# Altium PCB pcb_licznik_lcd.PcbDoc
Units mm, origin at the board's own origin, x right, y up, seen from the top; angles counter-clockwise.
Board outline 68.45 x 37.59 mm, 2 copper layers (Top Layer, Bottom Layer); 23 components, 34 nets, 133 pads, 10 vias.
Unrouted connection lines stored in the file: 5.
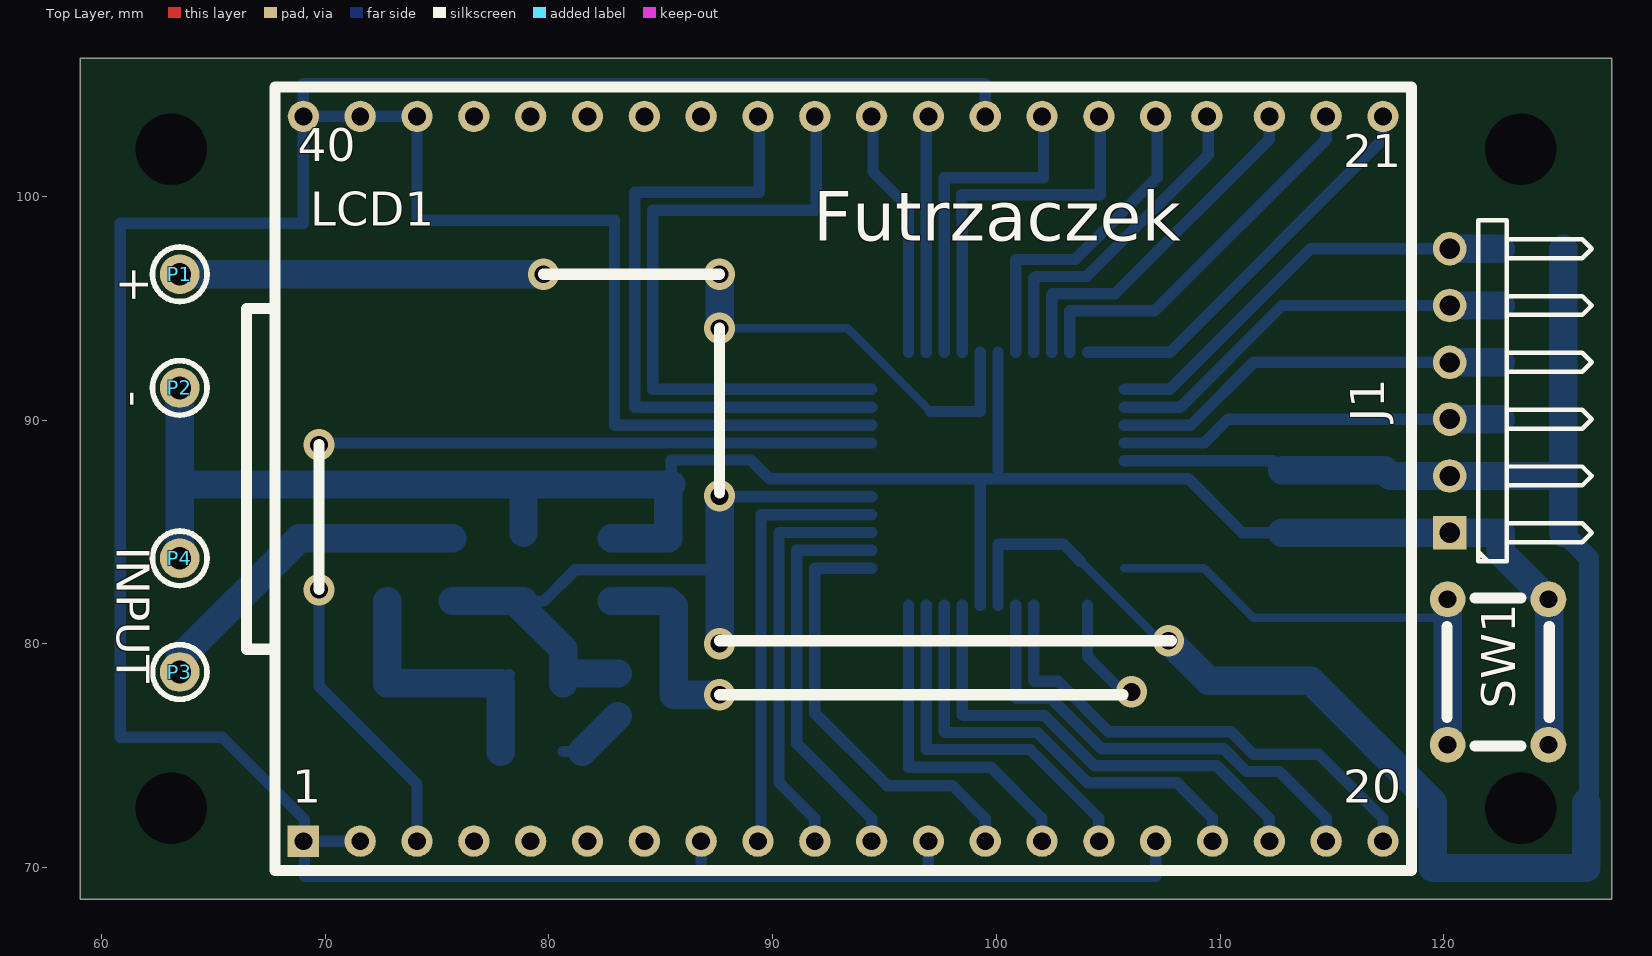
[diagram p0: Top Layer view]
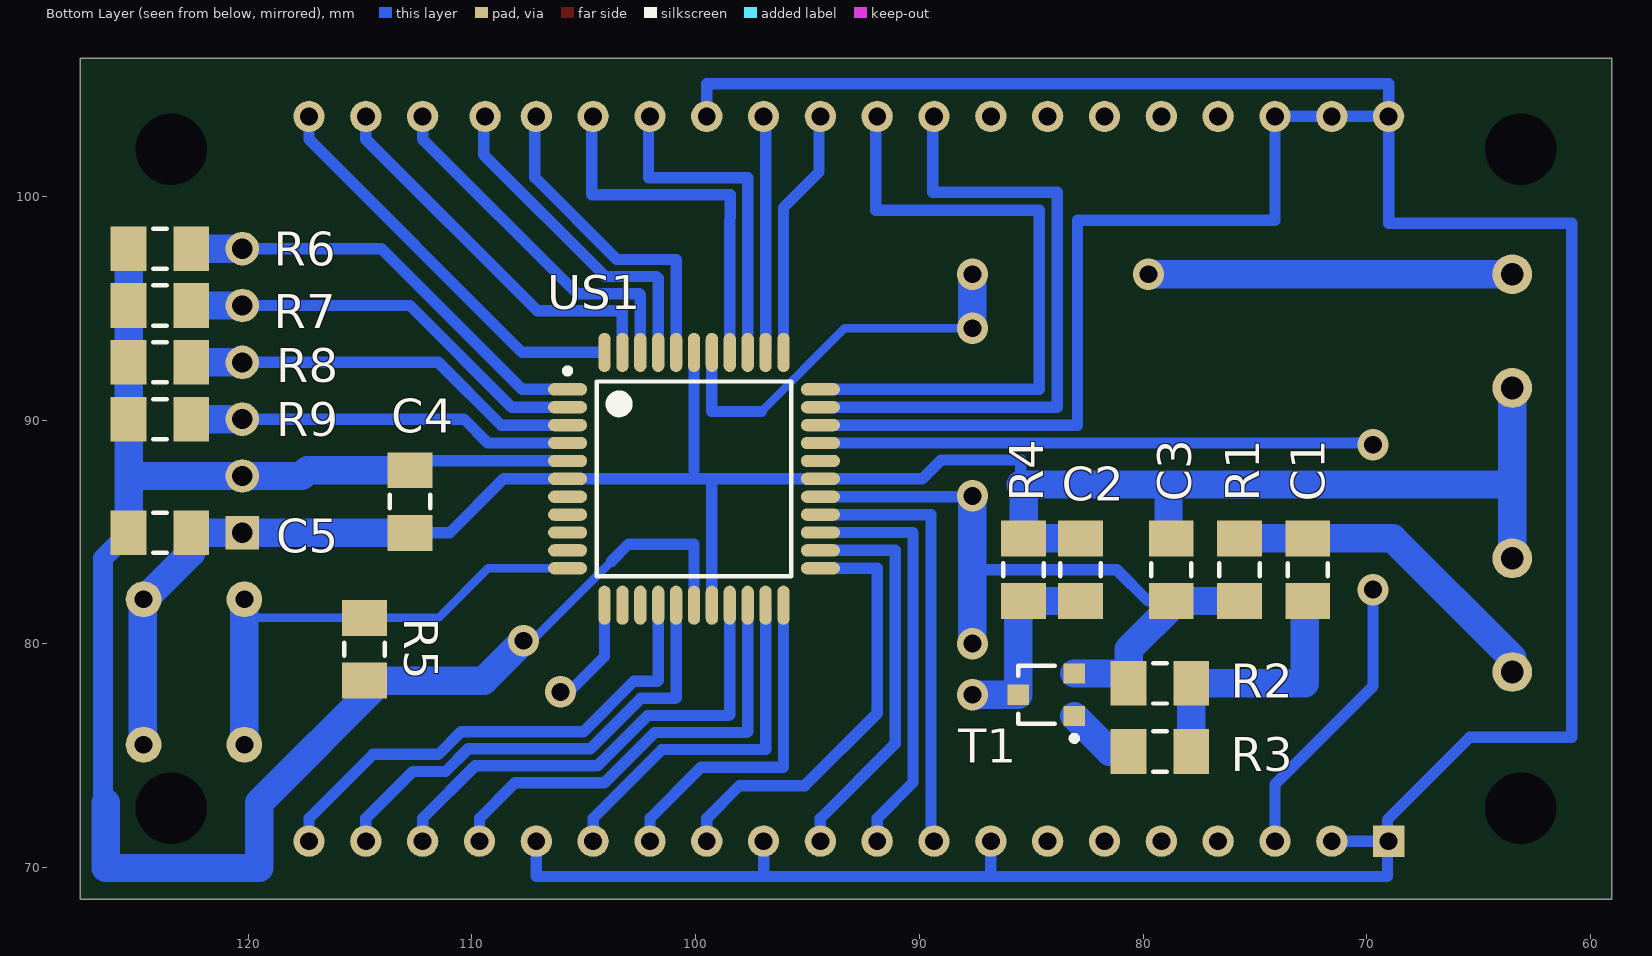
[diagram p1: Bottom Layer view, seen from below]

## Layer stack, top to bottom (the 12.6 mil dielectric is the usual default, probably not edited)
Top Layer: signal copper 0.0356
Dielectric: dielectric 0.32, FR-4, Dk 4.8
Bottom Layer: signal copper 0.0356

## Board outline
59.055,69.977 59.055,106.172 127.508,106.172 127.508,68.58 59.055,68.58

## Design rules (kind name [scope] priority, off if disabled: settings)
Clearance [All] p1: gap=0.254
PolygonConnect [All] p1: connectstyle=Relief reliefconductorwidth=0.254 reliefentries=4 polygonreliefangle="90 Angle"
RoutingVias [All] p1: holewidth=0.711 width=1.27 viastyle="Through Hole" minholewidth=0.711 minwidth=1.27 maxholewidth=0.711 maxwidth=1.27
SilkscreenOverComponentPads [All] p1: minsilkscreentomaskgap=0.254
SolderMaskExpansion [All] p1: expansion=0.102
Width [All] p1: maxlimit=1.27 minlimit=0.381 preferedwidth=0.508
27 further rules are at their usual default settings.

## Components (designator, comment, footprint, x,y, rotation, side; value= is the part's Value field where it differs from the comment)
C1 "100n" MELF-1206 72.644,83.312 r270 bottom
C2 "1u" MELF-1206 82.804,83.312 r270 bottom
C3 "1u" MELF-1206 78.74,83.312 r270 bottom
C4 "100n" MELF-1206 112.776,86.36 r90 bottom
C5 "100n" MELF-1206 123.952,84.963 r0 bottom
J1 "" HDR1X6H 120.269,84.963 r90 top
LCD1 "JH17" "LCD JH17" 94.426,87.376 r0 top
P1 "WE" "pad fi 1mm" 63.5,96.52 r0 top
P2 "WE" "pad fi 1mm" 63.5,91.44 r0 top
P3 "WE" "pad fi 1mm" 63.5,78.74 r0 top
P4 "WE" "pad fi 1mm" 63.5,83.82 r0 top
R1 "100k" MELF-1206 75.692,83.312 r90 bottom
R2 "10k" MELF-1206 79.248,78.232 r180 bottom
R3 "10k" MELF-1206 79.248,75.184 r0 bottom
R4 "10k" MELF-1206 85.344,83.312 r270 bottom
R5 "10k" MELF-1206 114.808,79.756 r270 bottom
R6 "10k" MELF-1206 123.952,97.663 r180 bottom
R7 "10k" MELF-1206 123.952,95.123 r180 bottom
R8 "10k" MELF-1206 123.952,92.583 r180 bottom
R9 "10k" MELF-1206 123.952,90.043 r180 bottom
SW1 "switch 6x6" "tact switch 6x6" 122.428,78.74 r270 top
T1 "BC856" 318-08 84.328,77.724 r90 bottom
US1 "ATmega32L" 44A_N 100.076,87.376 r180 bottom

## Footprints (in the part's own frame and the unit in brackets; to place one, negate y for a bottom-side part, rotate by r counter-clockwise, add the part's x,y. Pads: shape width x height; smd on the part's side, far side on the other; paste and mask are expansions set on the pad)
44A_N [mm] "Thin QFP, 44-Leads, Body 10x10mm, Pitch 0.8mm, IPC Medium Density"
  oval 1.75x0.55 smd: 1(-5.65,4) 2(-5.65,3.2) 3(-5.65,2.4) 4(-5.65,1.6) 5(-5.65,0.8) 6(-5.65,0) 7(-5.65,-0.8) 8(-5.65,-1.6) 9(-5.65,-2.4) 10(-5.65,-3.2) 11(-5.65,-4) 23(5.65,-4) 24(5.65,-3.2) 25(5.65,-2.4) 26(5.65,-1.6) 27(5.65,-0.8) 28(5.65,0) 29(5.65,0.8) 30(5.65,1.6) 31(5.65,2.4) 32(5.65,3.2) 33(5.65,4)
  oval 0.55x1.75 smd: 12(-4,-5.65) 13(-3.2,-5.65) 14(-2.4,-5.65) 15(-1.6,-5.65) 16(-0.8,-5.65) 17(0,-5.65) 18(0.8,-5.65) 19(1.6,-5.65) 20(2.4,-5.65) 21(3.2,-5.65) 22(4,-5.65) 34(4,5.65) 35(3.2,5.65) 36(2.4,5.65) 37(1.6,5.65) 38(0.8,5.65) 39(0,5.65) 40(-0.8,5.65) 41(-1.6,5.65) 42(-2.4,5.65) 43(-3.2,5.65) 44(-4,5.65)
  silkscreen extent -5.77,-4.35 4.35,4.95, body extent -5,-5 5,5, height 1.2
318-08 [mm] "SOT-23; 3 Leads; Body 3.0 x 2.6 mm, inc. leads (LxW max)"
  rect 0.9x0.95 smd: 1(-0.95,-1.25) 2(0.95,-1.25) 3(0,1.25)
  silkscreen extent -2.07,-1.37 1.3,1.25
HDR1X6H [mm] "Connector; Header; 6 Position; Right Angle"
  rect 1.5x1.5 hole 0.9: 1(0,0)
  round 1.5 hole 0.9: 2(2.54,0) 3(5.08,0) 4(7.62,0) 5(10.16,0) 6(12.7,0)
  silkscreen extent -1.27,-6.35 13.97,-1.27
"LCD JH17" [mm]
  rect 1.4x1.4 hole 0.8: 1(-25.4,-16.2)
  round 1.4 hole 0.8: 2(-22.86,-16.2) 3(-20.32,-16.2) 4(-17.78,-16.2) 5(-15.24,-16.2) 6(-12.7,-16.2) 7(-10.16,-16.2) 8(-7.62,-16.2) 9(-5.08,-16.2) 10(-2.54,-16.2) 11(0,-16.2) 12(2.54,-16.2) 13(5.08,-16.2) 14(7.62,-16.2) 15(10.16,-16.2) 16(12.7,-16.2) 17(15.24,-16.2) 18(17.78,-16.2) 19(20.32,-16.2) 20(22.86,-16.2) 21(22.86,16.2) 22(20.32,16.2) 23(17.78,16.2) 24(14.986,16.2) 25(12.7,16.2) 26(10.16,16.2) 27(7.62,16.2) 28(5.08,16.2) 29(2.54,16.2) 30(0,16.2) 31(-2.54,16.2) 32(-5.08,16.2) 33(-7.62,16.2) 34(-10.16,16.2) 35(-12.7,16.2) 36(-15.24,16.2) 37(-17.78,16.2) 38(-20.32,16.2) 39(-22.86,16.2) 40(-25.4,16.2)
  silkscreen extent -27.94,-17.51 24.13,17.51
MELF-1206 [mm] "Metal Electrode Face (MELF) Resistor; Body 3.2 x 1.8 mm (LxDia)"
  rect 1.6x2 smd: 1(-1.4,0) 2(1.4,0)
  silkscreen extent -0.3,-0.9 0.3,0.9, body extent -2.3,-1.1 2.3,1.1, height 1.85
"pad fi 1mm" [mil]
  round 70 hole 40: 1(0,0)
  silkscreen extent -48,-48 48,48
"tact switch 6x6" [mm]
  round 1.6 hole 0.8: 1(3.25,2.25) 2(3.25,-2.25) 3(-3.25,2.25) 4(-3.25,-2.25)
  silkscreen extent -3.3,-2.29 3.3,2.29

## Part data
C1 C2 C3 C4 C5: library part kondensator
J1: library part "Header 6H", "Header, 6-Pin, Right Angle"
LCD1: library part "LCD JH17"
P1 P2 P3 P4: library part Pad, "Pad"
R1 R2 R3 R4 R5 R6 R7 R8 R9: library part rezystor
SW1: library part switch
T1: library part BC856ALT1, "General Purpose Transistor PNP Silicon"
US1: library part ATmega32-16AC, "8-Bit AVR Microcontroller with 32K Bytes of In-System Programmable Flash Memory"

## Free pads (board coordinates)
  round 0 hole 3.2: 0(63.119,72.644) 1(63.119,102.108) 2(123.444,72.644) 3(123.444,102.108)

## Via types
v1: diameter 1.4, hole 0.8, Top Layer to Bottom Layer, 10 vias

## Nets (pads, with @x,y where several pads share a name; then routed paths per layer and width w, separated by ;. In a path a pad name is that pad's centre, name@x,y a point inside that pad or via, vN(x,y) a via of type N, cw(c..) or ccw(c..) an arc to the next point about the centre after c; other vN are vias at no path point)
GND: C2.1 C3.1 C4.1 C5.1 J1.1 P2.1 P4.1 R4.1 SW1.1 SW1.3 US1.6 US1.18 US1.28 US1.39 | length 101.6
  Bottom Layer w0.508: 85.471,87.122 85.471,88.214 89.027,88.214 89.865,87.376 US1.28 US1.6 108.585,87.376 111.001,84.96 C4.1 ; US1.18 99.276,87.287 ; 100.076,87.757 US1.39
  Bottom Layer w1.27: P4.1 63.5,87.376 ; P2.1 63.5,87.376 ; C3.1@78.867,84.966 78.867,87.122 ; 81.534,87.122 78.867,87.122 ; C2.1 R4.1 85.344,86.995 ; 85.471,87.122 78.867,87.122 ; C4.1@112.779,84.963 J1.1 ; C5.1@121.793,84.963 J1.1 ; SW1.1@124.714,75.49 124.714,81.915 122.552,84.077 C5.1 J1.1 ; 63.5,87.376 63.754,87.122 78.867,87.122
NetC1_1: C1.1 P3.1 R1.2 | length 15
  Bottom Layer w1.27: P3.1 63.5,79.375 68.837,84.712 74.676,84.712 R1.2
NetC1_2: C1.2 R2.2 R3.1 | length 12.3
  Bottom Layer w0.508: R2.2 R2.2@78.232,78.616
  Bottom Layer w1.27: C1.2@72.771,81.912 72.771,78.232 R2.2 R3.1
NetC2_2: C2.2 R4.2 T1.3 US1.12 | length 13.4
  Bottom Layer w0.508: US1.12 104.076,79.439 v1@105.664,77.851
  Bottom Layer w1.27: C2.2 R4.2 85.578,81.678 T1.3 v1(87.63,77.724)
  other v1: 106.045,77.851
NetJ1_3: J1.3 R9.2 US1.4 | length 18.8
  Bottom Layer w0.508: US1.4 109.296,88.976 110.363,90.043 R9.2@121.793,90.043
  Bottom Layer w1.27: J1.3 R9.2
NetJ1_4: J1.4 R8.2 US1.3 | length 19.5
  Bottom Layer w0.508: US1.3 108.699,89.776 111.506,92.583 R8.2@121.793,92.583
  Bottom Layer w1.27: J1.4 R8.2
NetJ1_5: J1.5 R7.2 US1.2 | length 20.2
  Bottom Layer w0.508: US1.2 108.229,90.576 112.776,95.123 R7.2@121.793,95.123
  Bottom Layer w1.27: J1.5 R7.2
NetJ1_6: J1.6 R6.2 US1.1 | length 21
  Bottom Layer w0.508: US1.1 107.759,91.376 114.046,97.663 R6.2@121.793,97.663
  Bottom Layer w1.27: J1.6 R6.2
NetLCD1_1: LCD1.1 LCD1.2 LCD1.8 LCD1.12 LCD1.16 LCD1.28 LCD1.38 LCD1.39 LCD1.40 US1.31 | length 166.1
  Bottom Layer w0.508: LCD1.1 LCD1.1@69.075,71.176 ; LCD1.2 LCD1.1@69.075,71.176 ; 86.806,69.658 LCD1.8 ; US1.31 82.931,89.776 82.931,98.933 74.106,98.933 LCD1.38 LCD1.39 LCD1.40 ; 96.966,69.658 LCD1.12 ; LCD1.28@99.501,103.572 99.501,105.029 69.026,105.029 LCD1.40 ; LCD1.16 107.126,69.596 69.075,69.596 LCD1.1@69.075,71.176 ; LCD1.40 69.026,98.806 60.833,98.806 60.833,75.819 65.405,75.819 69.075,72.149 LCD1.1@69.075,71.176
NetLCD1_3: LCD1.3 US1.30 | length 37.8
  Bottom Layer w0.508: v1(69.723,82.423) 69.723,78.105 74.106,73.722 LCD1.3 ; v1(69.723,88.9) 69.799,88.976 US1.30
NetLCD1_9: LCD1.9 US1.26 | length 19.5
  Bottom Layer w0.508: LCD1.9@89.484,71.176 89.484,85.776 US1.26
NetLCD1_10: LCD1.10 US1.25 | length 18.6
  Bottom Layer w0.508: LCD1.10 91.886,72.198 90.284,73.8 90.284,84.976 US1.25
NetLCD1_11: LCD1.11 US1.24 | length 17.7
  Bottom Layer w0.508: LCD1.11 94.426,72.198 91.084,75.54 91.084,84.176 US1.24
NetLCD1_13: LCD1.13 US1.23 | length 19.6
  Bottom Layer w0.508: US1.23 91.884,83.376 91.884,76.899 95.123,73.66 98.044,73.66 99.506,72.198 LCD1.13
NetLCD1_14: LCD1.14 US1.22 | length 15.2
  Bottom Layer w0.508: US1.22 96.076,74.486 99.758,74.486 102.046,72.198 LCD1.14
NetLCD1_15: LCD1.15 US1.21 | length 16.5
  Bottom Layer w0.508: US1.21 96.876,75.273 101.511,75.273 104.586,72.198 LCD1.15
NetLCD1_17: LCD1.17 US1.20 | length 20.3
  Bottom Layer w0.508: US1.20 97.676,76.073 97.714,76.035 101.827,76.035 104.075,73.787 108.077,73.787 109.666,72.198 LCD1.17
NetLCD1_18: LCD1.18 US1.19 | length 21.6
  Bottom Layer w0.508: US1.19 98.476,76.835 98.514,76.797 102.142,76.797 104.39,74.549 109.855,74.549 112.206,72.198 LCD1.18
NetLCD1_19: LCD1.19 US1.16 | length 21.3
  Bottom Layer w0.508: US1.16 100.876,77.597 100.914,77.559 102.458,77.559 104.706,75.311 110.171,75.311 111.187,74.295 112.649,74.295 114.746,72.198 LCD1.19
NetLCD1_20: LCD1.20 US1.15 | length 22.6
  Bottom Layer w0.508: US1.15 101.676,78.359 101.714,78.321 102.774,78.321 105.022,76.073 110.486,76.073 111.502,75.057 114.427,75.057 117.286,72.198 LCD1.20
NetLCD1_21: LCD1.21 US1.44 | length 18.2
  Bottom Layer w0.508: US1.44 107.758,93.026 117.286,102.554 LCD1.21
NetLCD1_22: LCD1.22 US1.43 | length 17.5
  Bottom Layer w0.508: US1.43 103.276,94.894 107.086,94.894 114.746,102.554 LCD1.22
NetLCD1_23: LCD1.23 US1.42 | length 16.2
  Bottom Layer w0.508: US1.42 102.476,95.618 102.514,95.656 105.308,95.656 112.206,102.554 LCD1.23
NetLCD1_24: LCD1.24 US1.41 | length 15.1
  Bottom Layer w0.508: US1.41 101.676,96.342 101.752,96.418 104.038,96.418 109.474,101.854 LCD1.24@109.474,103.576
NetLCD1_25: LCD1.25 US1.40 | length 14.7
  Bottom Layer w0.508: US1.40 100.876,97.18 103.53,97.18 107.188,100.838 LCD1.25@107.188,103.576
NetLCD1_26: LCD1.26 US1.37 | length 16.7
  Bottom Layer w0.508: US1.37 98.476,97.917 98.463,100.076 99.2,100.076 104.648,100.076 LCD1.26@104.648,103.576
NetLCD1_27: LCD1.27 US1.36 | length 15
  Bottom Layer w0.508: US1.36 97.676,100.838 97.999,100.838 98,100.839 98.926,100.839 98.928,100.838 100.33,100.838 102.108,100.838 LCD1.27@102.108,103.576
NetLCD1_29: LCD1.29 US1.35 | length 10.5
  Bottom Layer w0.508: US1.35 96.876,102.464 LCD1.29@96.876,103.486
NetLCD1_30: LCD1.30 US1.34 | length 11.1
  Bottom Layer w0.508: LCD1.30@94.488,103.514 94.488,101.092 96.076,99.504 US1.34
NetLCD1_31: LCD1.31 US1.33 | length 29.2
  Bottom Layer w0.508: LCD1.31@91.948,103.514 91.948,99.378 84.645,99.378 84.645,91.376 US1.33
NetLCD1_32: LCD1.32 US1.32 | length 29.1
  Bottom Layer w0.508: LCD1.32@89.408,103.514 89.408,100.178 83.845,100.178 83.845,90.576 US1.32
NetR3_2: R3.2 T1.1 | length 3.1
  Bottom Layer w0.508: R3.2 81.488,75.184
  Bottom Layer w1.27: 81.488,75.184 T1.1
NetR5_1: R5.1 SW1.2 SW1.4 US1.11 | length 22
  Bottom Layer w0.381: US1.11 109.283,83.376 111.503,81.156 R5.1 120.336,81.156
  Bottom Layer w1.27: SW1.2 SW1.4
VCC: C3.2 C4.2 C5.2 J1.2 P1.1 R1.1 R2.1 R5.2 R6.1 R7.1 R8.1 R9.1 T1.2 US1.5 US1.17 US1.27 US1.38 | length 153.4
  Bottom Layer w0.381: v1(87.63,94.107) 93.345,94.107 97.066,90.386 ; 103.759,83.693 107.315,80.137 v1(107.696,80.137) ; C5.2 C5.2@125.73,84.585
  Bottom Layer w0.508: C3.2@78.867,81.915 79.781,81.915 81.178,83.312 87.63,83.312 ; v1@87.668,86.576 US1.27 ; 97.066,90.386 99.276,90.386 US1.38 ; US1.17 100.076,84.455 102.997,84.455 103.759,83.693 ; US1.5 112.36,88.176 C4.2
  Bottom Layer w0.889: C5.2 126.492,83.823 126.492,73.025
  Bottom Layer w1.27: P1.1 v1(79.756,96.52) ; R1.1 C3.2@78.867,81.915 ; C3.2@78.613,81.788 80.648,79.753 R2.1 ; R2.1@81.09,78.674 T1.2 ; v1(87.63,80.01) 87.63,83.312 v1(87.63,86.614) ; v1(87.63,94.107) v1(87.63,96.52) ; v1(107.696,80.137) 109.477,78.356 114.049,78.356 119.507,72.898 119.507,69.977 126.365,69.977 126.365,72.898 ; C4.2 117.345,87.76 117.602,87.503 121.793,87.503 ; J1.2 125.225,87.503 ; C5.2 R9.1 R8.1 R7.1 R6.1
pads on no net: LCD1.4 LCD1.5 LCD1.6 LCD1.7 LCD1.33 LCD1.34 LCD1.35 LCD1.36 LCD1.37 US1.7 US1.8 US1.9 US1.10 US1.13 US1.14 US1.29

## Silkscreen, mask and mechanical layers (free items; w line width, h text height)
Top Overlay:
  lines w0.5: 69.723,82.423 69.723,88.9 ; 79.756,96.52 87.63,96.52 ; 87.63,77.724 105.664,77.724 ; 87.63,80.137 107.823,80.137 ; 87.63,86.741 87.63,94.107
  text "Futrzaczek" at 91.821,97.282 h3.81
  text "+      -" at 60.325,96.901 h2.54 r270
  text "INPUT" at 60.198,84.328 h2.54 r270
Mechanical 1:
  the board outline again, w0.5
